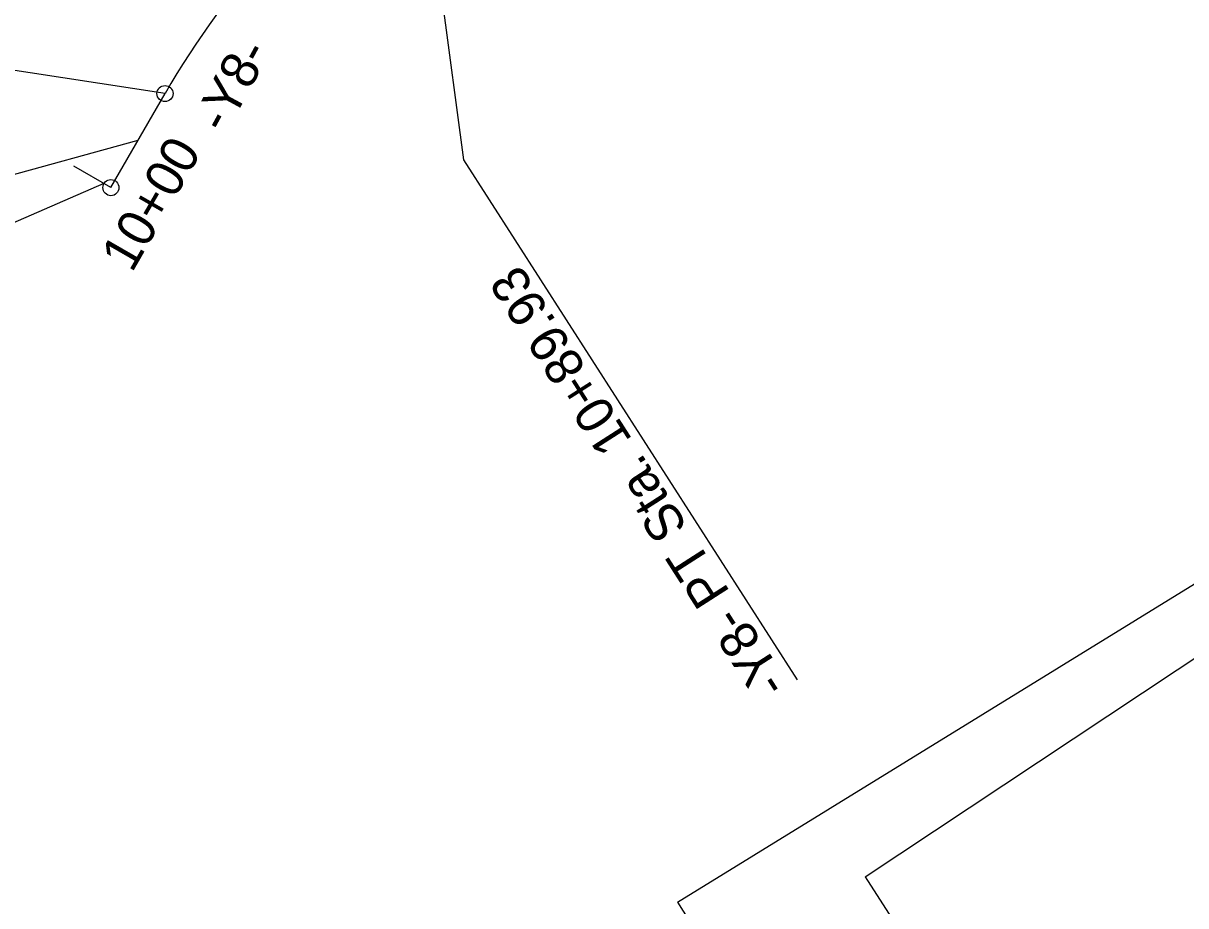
# Model space of a CAD drawing. Extents: x 472216 to 481979, y 489069 to 507339.
# Drawn here: x 477468 to 477685.2, y 499233.6 to 499398.5 of the extents above; entities that cross this region are included whole.
import ezdxf

# ---------------------------------------------------------------- set-up
doc = ezdxf.new("R2010")
doc.units = 0
for name, color, linetype in [('Old_Level_12', 7, 'Continuous'), ('Sheet North Arrow Point CELL', 7, 'Continuous'), ('Sheet Plan And Profile CELL', 7, 'Continuous'), ('Sheet Profile Grid Major CELL', 7, 'Continuous'), ('Sheet Profile Grid Minor CELL', 7, 'Continuous')]:
    doc.layers.add(name, color=color, linetype=linetype)

msp = doc.modelspace()

# ---------------------------------------------------------------- linework, layer by layer
at = {"layer": 'Old_Level_12'}
for p, q in [((477541.97, 499435.17), (477550.29, 499372.98)), ((477494.5, 499385.36), (477428.17, 499395.59)), ((477489.45, 499376.58), (477370.34, 499343.85)), ((477550.29, 499372.98), (477612.62, 499275.82)), ((477483.09, 499368.54), (477356.6, 499313.75)), ((477590.23, 499234.32), (477778.77, 499350.31)), ((477625.35, 499239.03), (477781.61, 499342.81)), ((477625.35, 499239.03), (477676.48, 499159.33)), ((477590.23, 499234.32), (477641.36, 499154.62))]:
    msp.add_line(p, q, dxfattribs=at)
for centre in [(477494.5, 499385.36), (477494.5, 499385.36), (477484.39, 499367.79), (477484.39, 499367.79)]:
    msp.add_circle(centre, 1.5, dxfattribs=at)
at = {"layer": 'Sheet North Arrow Point CELL'}
msp.add_line((477484.39, 499367.79), (477494.5, 499385.36), dxfattribs=at)
msp.add_line((477484.39, 499367.79), (477494.5, 499385.36), dxfattribs=at)
for centre, radius, start, end in [((475792.47, 498595.18), 2125, 7.92268, 31.27221), ((477633.16, 499305.52), 160, 125.1222, 150.0686), ((477633.16, 499305.52), 160, 125.1222, 150.0686)]:
    msp.add_arc(centre, radius, start, end, dxfattribs=at)
at = {"layer": 'Sheet Profile Grid Minor CELL'}
msp.add_line((477484.39, 499367.79), (477477.46, 499371.79), dxfattribs=at)

# ---------------------------------------------------------------- texts
at = {"layer": 'Old_Level_12'}
msp.add_text('-Y8- PT Sta. 10+89.93', height=7, rotation=122.6818, dxfattribs=at).set_placement((477611.15, 499275.12))
at = {"layer": 'Sheet Plan And Profile CELL'}
msp.add_text('-Y8-', height=7, rotation=61.4119, dxfattribs=at).set_placement((477505.78, 499377.62))
at = {"layer": 'Sheet Profile Grid Major CELL'}
msp.add_text('10+00', height=7, rotation=60.0686, dxfattribs=at).set_placement((477488.3, 499351.73))

doc.saveas('drawing.dxf')
